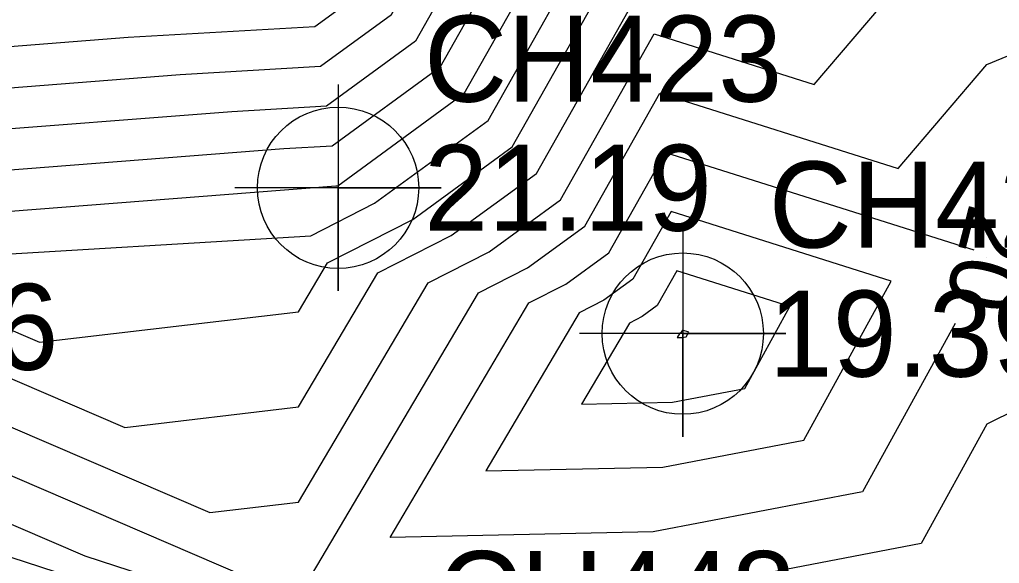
# Model space of a CAD drawing. Extents: x 2531902 to 2533249, y 715219 to 716099.
# Drawn here: x 2532941.89 to 2532970.37, y 715621.1 to 715636.9 of the extents above; entities that cross this region are included whole.
import ezdxf

# ---------------------------------------------------------------- set-up
doc = ezdxf.new("R2010")
doc.units = 0
for name, color, linetype in [('DTM Contours Major', 7, 'Continuous'), ('DTM Contours Major Text', 7, 'Continuous'), ('DTM Contours Minor', 7, 'Continuous'), ('Exist DTM Breakline Cogo Number', 7, 'Continuous'), ('Exist DTM QL2 LIDAR Elevation Point', 7, 'Continuous'), ('Exist DTM Regular Point CELL', 7, 'Continuous'), ('Exist DTM Regular Point Cogo Elevation', 7, 'Continuous'), ('Exist DTM Regular Point Cogo Number', 7, 'Continuous')]:
    doc.layers.add(name, color=color, linetype=linetype)

msp = doc.modelspace()

# ---------------------------------------------------------------- linework, layer by layer
at = {"layer": 'DTM Contours Major'}
for points in [[(2532930.163, 715650.099), (2532929.898, 715650.158), (2532929.571, 715650), (2532924.378, 715645.678), (2532920, 715643.017), (2532917.483, 715641.592), (2532912.377, 715640), (2532919.647, 715638.57), (2532924.48, 715635.52), (2532929.94, 715633.104), (2532931.756, 715631.756), (2532939.999, 715630), (2532940, 715630), (2532940.001, 715629.999), (2532940.005, 715630), (2532950.352, 715630.619), (2532952.209, 715631.564), (2532955.506, 715633.97), (2532958.913, 715640), (2532956.632, 715644.23), (2532946.757, 715649.657), (2532939.991, 715651.642), (2532937.153, 715651.196)], [(2532935.903, 715637.286), (2532936.697, 715636.697), (2532940, 715635.993), (2532945.045, 715636.386), (2532950.474, 715636.702), (2532951.996, 715637.813), (2532953.232, 715640), (2532952.405, 715641.534)], [(2532952.662, 715621.854), (2532956.69, 715628.666), (2532957.764, 715629.213), (2532959.015, 715630.126), (2532960.662, 715633.04), (2532969.626, 715630.211)], [(2532969.077, 715628.068), (2532966.385, 715623.18), (2532960.301, 715622.013), (2532952.662, 715621.854)], [(2532935.894, 715624.711), (2532943.783, 715621.321), (2532950.358, 715619.175), (2532957.857, 715619.103), (2532964.274, 715616.784), (2532973.377, 715614.761), (2532979.797, 715608.393), (2532986.643, 715608.537), (2532989.98, 715607.327), (2532995.636, 715600.526), (2533006.735, 715593.678), (2533017.706, 715587.707), (2533019.99, 715586.297), (2533023.347, 715583.535)]]:
    msp.add_lwpolyline(points, dxfattribs=at)
at = {"layer": 'DTM Contours Minor'}
for points in [[(2532939.994, 715651.153), (2532944.745, 715649.759), (2532955.787, 715643.691), (2532957.777, 715640), (2532954.804, 715634.738), (2532951.14, 715632.064), (2532951.081, 715632.061), (2532940, 715631.198), (2532932.744, 715632.744), (2532929.906, 715634.85), (2532921.375, 715638.625), (2532919.892, 715639.561), (2532917.66, 715640), (2532919.227, 715640.489), (2532920, 715640.926), (2532925.689, 715644.384), (2532929.957, 715647.936), (2532932.651, 715650), (2532939.994, 715651.153)], [(2532939.996, 715650.664), (2532942.732, 715649.861), (2532954.941, 715643.152), (2532956.641, 715640), (2532954.102, 715635.507), (2532950.973, 715633.224), (2532949.572, 715633.142), (2532940, 715632.397), (2532933.732, 715633.732), (2532929.872, 715636.597), (2532922.027, 715640.067), (2532927, 715643.09), (2532929.907, 715645.509), (2532935.768, 715650), (2532939.996, 715650.664)], [(2532939.999, 715650.175), (2532940.719, 715649.963), (2532954.096, 715642.612), (2532955.504, 715640), (2532953.4, 715636.276), (2532950.807, 715634.383), (2532948.063, 715634.223), (2532940, 715633.596), (2532934.721, 715634.721), (2532929.838, 715638.343), (2532925.667, 715640.189), (2532928.311, 715641.796), (2532929.856, 715643.082), (2532938.886, 715650), (2532939.999, 715650.175)], [(2532953.25, 715642.073), (2532941.432, 715648.568), (2532940, 715648.711), (2532931.576, 715642.011), (2532929.806, 715640.655), (2532929.621, 715640.501), (2532929.306, 715640.31), (2532929.804, 715640.089), (2532935.709, 715635.709), (2532940, 715634.794), (2532946.554, 715635.304), (2532950.64, 715635.543), (2532952.698, 715637.045), (2532954.368, 715640), (2532953.25, 715642.073)], [(2532909.09, 715638.585), (2532912.594, 715636.841), (2532918.913, 715635.598), (2532927.584, 715630.125), (2532930.026, 715628.675), (2532935.825, 715627.561), (2532947.422, 715622.578), (2532950, 715622.88), (2532953.766, 715629.249), (2532955.542, 715630.153), (2532957.612, 715631.664), (2532960.334, 715636.483), (2532964.985, 715635.015), (2532969.239, 715640)], [(2532919.402, 715637.58), (2532927.586, 715632.414), (2532929.974, 715631.358), (2532930.768, 715630.768), (2532934.374, 715630), (2532938.608, 715629.187), (2532942.474, 715627.526), (2532950, 715628.408), (2532950.842, 715629.832), (2532953.32, 715631.094), (2532956.208, 715633.201), (2532960.007, 715639.925)], [(2532908.734, 715638.031), (2532913.611, 715635.602), (2532918.668, 715634.607), (2532925.608, 715630.227), (2532930.047, 715627.591), (2532934.434, 715626.749), (2532949.896, 715620.104), (2532950, 715620.117), (2532955.228, 715628.958), (2532956.653, 715629.683), (2532958.314, 715630.895), (2532960.498, 715634.761), (2532967.425, 715632.575), (2532970, 715635.594), (2532979.55, 715639.55)], [(2532911.577, 715638.08), (2532919.158, 715636.589), (2532929.56, 715630.023), (2532930.005, 715629.759), (2532937.217, 715628.374), (2532944.948, 715625.052), (2532950, 715625.644), (2532952.304, 715629.541), (2532954.431, 715630.624), (2532956.91, 715632.432), (2532960.171, 715638.204)], [(2532908.02, 715636.921), (2532915.645, 715633.124), (2532918.179, 715632.626), (2532921.656, 715630.431), (2532930.089, 715625.423), (2532931.651, 715625.123), (2532937.292, 715622.699), (2532950.731, 715618.313), (2532955.853, 715618.265), (2532968.273, 715613.775), (2532974.972, 715612.286)], [(2532967.221, 715629.3), (2532960.825, 715631.319), (2532959.717, 715629.357), (2532958.875, 715628.743), (2532958.152, 715628.375), (2532955.441, 715623.789), (2532960.583, 715623.897), (2532964.678, 715624.682), (2532967.221, 715629.3)], [(2532979.818, 715630), (2532970, 715625.141), (2532968.093, 715621.678), (2532960.019, 715620.13), (2532953.796, 715620), (2532959.862, 715619.942), (2532960.276, 715619.792), (2532971.782, 715617.235)], [(2532964.279, 715628.559), (2532960.989, 715629.597), (2532960.419, 715628.589), (2532959.986, 715628.272), (2532959.614, 715628.083), (2532958.22, 715625.725), (2532960.864, 715625.78), (2532962.971, 715626.184), (2532964.279, 715628.559)], [(2532961.336, 715627.818), (2532961.153, 715627.876), (2532961.121, 715627.82), (2532961.097, 715627.802), (2532961.076, 715627.792), (2532960.999, 715627.66), (2532961.146, 715627.663), (2532961.263, 715627.686), (2532961.336, 715627.818)]]:
    msp.add_lwpolyline(points, dxfattribs=at)
at = {"layer": 'Exist DTM QL2 LIDAR Elevation Point'}
for p, q in [((2532950, 715630), (2532950, 715630)), ((2532970, 715630), (2532970, 715630))]:
    msp.add_line(p, q, dxfattribs=at)
at = {"layer": 'Exist DTM Regular Point CELL'}
for points in [[(2532951.147, 715635.014), (2532951.147, 715629.014), (2532951.147, 715632.014), (2532954.147, 715632.014), (2532948.147, 715632.014)], [(2532961.163, 715630.775), (2532961.163, 715624.775), (2532961.163, 715627.775), (2532964.163, 715627.775), (2532958.163, 715627.775)]]:
    msp.add_lwpolyline(points, dxfattribs=at)
for centre in [(2532951.147, 715632.014), (2532961.163, 715627.775)]:
    msp.add_circle(centre, 2.344, dxfattribs=at)

# ---------------------------------------------------------------- texts
at = {"layer": 'DTM Contours Major Text'}
msp.add_text('20', height=2, rotation=255.6207, dxfattribs=at).set_placement((2532969.514, 715631.609))
at = {"layer": 'Exist DTM Breakline Cogo Number'}
for s, p in [('CH446', (2532932.612, 715626.724)), ('CH448', (2532954.035, 715618.957))]:
    msp.add_text(s, height=2.5, dxfattribs=at).set_placement(p)
at = {"layer": 'Exist DTM Regular Point Cogo Elevation'}
for s, p in [('21.19', (2532953.647, 715630.764)), ('19.39', (2532963.663, 715626.525))]:
    msp.add_text(s, height=2.5, dxfattribs=at).set_placement(p)
at = {"layer": 'Exist DTM Regular Point Cogo Number'}
for s, p in [('CH423', (2532953.647, 715634.514)), ('CH424', (2532963.663, 715630.275))]:
    msp.add_text(s, height=2.5, dxfattribs=at).set_placement(p)

doc.saveas('drawing.dxf')
